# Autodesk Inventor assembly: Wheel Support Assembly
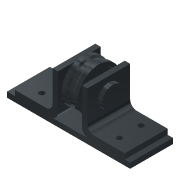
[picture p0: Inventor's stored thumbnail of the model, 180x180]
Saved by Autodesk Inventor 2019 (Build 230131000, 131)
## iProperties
Created: 2016-08
Part Number: Wheel Support Assembly
Document SubType Name: Assembly
Designer: Sandeep
Author: Sandeep
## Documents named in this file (5)
- E:\_Deepak\Inventor\Projects\Autodesk Inventor_2019_Project\Resources\Input files\c15_Inv_tut_2019\c15_tut03_inv\Wheel Support Assembly.iam
- E:\_Deepak\Inventor\Projects\Autodesk Inventor_2019_Project\Resources\Input files\c15_Inv_tut_2019\c15_tut03_inv\base.ipt
- E:\_Deepak\Inventor\Projects\Autodesk Inventor_2019_Project\Resources\Input files\c15_Inv_tut_2019\c15_tut03_inv\Support.ipt
- E:\_Deepak\Inventor\Projects\Autodesk Inventor_2019_Project\Resources\Input files\c15_Inv_tut_2019\c15_tut03_inv\Wheel.ipt
- E:\_Deepak\Inventor\Projects\Autodesk Inventor_2019_Project\Resources\Input files\c15_Inv_tut_2019\c15_tut03_inv\Shoulder screw.ipt
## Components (5 placed, 4 different names)
1. base:1 — Insert:1, Mate:1, Insert:2, Mate:2
2. Support:1 — Insert:1, Mate:1, Insert:3
3. Support:2 — Insert:2, Mate:2, Mate:3, Mate:4
4. Wheel:1 — Insert:3
5. Shoulder screw:1 — Mate:3, Mate:4
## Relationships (7: Mate 4, Insert 3)
- Insert:1: base:1 ↔ Support:1
- Mate:1: base:1 ↔ Support:1
- Insert:2: base:1 ↔ Support:2
- Mate:2: base:1 ↔ Support:2
- Insert:3: Support:1 ↔ Wheel:1
- Mate:3: Support:2 ↔ Shoulder screw:1
- Mate:4: Support:2 ↔ Shoulder screw:1
